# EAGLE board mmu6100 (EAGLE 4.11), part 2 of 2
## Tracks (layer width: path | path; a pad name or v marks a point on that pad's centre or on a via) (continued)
MA6  (via drill 0.61) (continued)
  Bottom 0.254: v95.89,80.64 96.52,81.28 114.3,81.28 v114.94,80.64 | v135.89,69.85 v119.38,69.85 | v139.06,73.66 149.86,73.66 150.5,74.3 180.97,74.3 v181.61,73.66 | IC39.5 161.29,106.68 162.56,105.41 176.53,105.41 177.8,106.68 IC38.5
MA7  (via drill 0.61)
  Top 0.254: v87.63,45.72 87,45.09 v87,30.48 | v81.92,29.21 79.38,31.75 79.38,37.47 v76.2,40.64 | v32.38,42.55 33.02,43.18 33.02,118.75 34.92,120.65 v34.92,125.73 | v117.47,125.09 118.75,126.36 v118.75,135.89 | v139.06,130.81 139.7,130.18 v139.7,128.27 | v161.93,128.27 161.93,106.05 IC39.6
  Bottom 0.254: v87,30.48 85.72,29.21 v81.92,29.21 | v76.2,40.64 75.56,41.27 69.22,41.27 67.94,40.01 34.92,40.01 v32.38,42.55 | v34.92,125.73 36.83,127.64 80.01,127.64 81.92,125.73 94.61,125.73 95.25,126.36 97.16,126.36 99.06,124.46 109.86,124.46 110.49,125.09 v117.47,125.09 | v118.75,135.89 123.19,135.89 128.27,130.81 v139.06,130.81 | v139.7,128.27 v161.93,128.27 | v87.63,45.72 IC5.12 | IC38.6 181.61,104.14 180.97,103.5 177.16,103.5 176.53,102.87 162.56,102.87 161.29,104.14 IC39.6
MA8  (via drill 0.61)
  Top 0.254: v85.72,41.27 85.72,43.81 IC5.9 | v111.76,43.18 v109.86,41.27 | v133.35,43.18 135.25,45.09 135.25,59.05 135.89,59.69 139.06,59.69 139.06,64.14 138.43,64.77 135.25,64.77 135.25,66.67 146.05,77.47 149.22,77.47 149.22,73.03 150.5,71.75 151.13,71.75 151.13,72.39 155.57,76.83 155.57,87.63 154.94,88.27 v154.94,101.6
  Bottom 0.254: v85.72,41.27 98.42,41.27 99.06,41.91 109.22,41.91 v109.86,41.27 | v111.76,43.18 113.03,41.91 132.08,41.91 v133.35,43.18 | v154.94,101.6 IC39.7 161.93,101.6 163.19,100.33 180.34,100.33 181.61,101.6 IC38.7
MA9  (via drill 0.61)
  Top 0.254: v87,76.83 v87,53.34 | v127,77.47 130.18,80.64 v130.18,83.19 | v161.93,85.09 162.56,84.45 v162.56,81.28
  Bottom 0.254: v87,76.83 87.63,76.2 109.86,76.2 111.12,77.47 v127,77.47 | v130.18,83.19 132.08,85.09 v161.93,85.09 | v162.56,81.28 184.78,81.28 196.22,92.71 196.22,95.25 199.39,95.25 200.03,95.89 200.03,97.79 186.06,97.79 184.78,99.06 IC38.8 180.34,99.06 179.07,97.79 162.56,97.79 161.29,99.06 IC39.8 | v87,53.34 IC5.6
MA10  (via drill 0.61)
  Top 0.254: v88.27,69.22 v88.27,55.88 | v137.16,70.48 148.59,81.92 v148.59,95.25 | v161.93,92.71 161.93,94.61 IC39.9
  Bottom 0.254: v88.27,69.22 108.58,69.22 110.49,71.12 136.53,71.12 v137.16,70.48 | v148.59,95.25 157.48,95.25 158.75,96.52 IC39.9 | v88.27,55.88 IC5.5 | v161.93,92.71 184.78,92.71 184.78,94.61 IC38.9
MA11  (via drill 0.61)
  Top 0.254: v88.9,3.17 88.27,3.81 88.27,9.53 88.9,10.16 88.9,49.53 82.55,49.53 81.92,50.16 81.92,61.59 IC5.2 | v99.06,3.17 100.33,1.91 109.22,1.91 v109.22,11.43 | v205.74,7.62 210.19,12.06 210.19,41.91 208.91,43.18 208.91,46.35 210.82,48.26 210.82,100.33 v210.19,100.97 | v187.32,101.6 184.78,99.06 184.78,95.89 IC38.10
  Bottom 0.254: v88.9,3.17 89.53,2.54 98.42,2.54 v99.06,3.17 | v109.22,11.43 139.7,11.43 143.51,7.62 v205.74,7.62 | v210.19,100.97 209.55,100.33 196.85,100.33 195.58,101.6 v187.32,101.6 | IC39.10 172.72,93.98 173.99,95.25 180.34,95.25 181.61,93.98 IC38.10
MEMDX0  (via drill 0.61)
  Top 0.254: v172.72,101.6 173.35,100.97 173.35,85.72 IC39.15 175.9,83.19 v175.9,71.75 | v182.88,10.16 182.88,25.4 IC15.1 186.06,28.57 186.06,30.48 v191.77,36.2 | v147.96,10.16 143.51,14.61 143.51,18.41 144.78,19.68 SV1.35 | v180.97,71.12 182.25,69.85 182.25,62.87 v181.61,62.23 | v196.22,62.23 v196.22,40.64
  Bottom 0.254: v172.72,101.6 172.09,102.23 161.93,102.23 161.29,102.87 157.48,102.87 153.67,106.68 IC9.18 | v182.88,10.16 v147.96,10.16 | v175.9,71.75 176.53,71.12 v180.97,71.12 | v196.22,62.23 v181.61,62.23 | v196.22,40.64 v191.77,36.2
MEMDX1  (via drill 0.61)
  Top 0.254: 156.21,81.92 156.21,80.64 157.48,79.38 158.75,79.38 158.75,82.55 158.12,83.19 158.12,84.45 IC39.13 | 156.21,81.92 156.21,88.27 155.57,88.9 155.57,97.79 156.21,98.42 156.21,101.6 153.67,104.14 IC9.17 | v20.95,120.65 20.95,130.18 IC3.6 | v63.5,80.64 v63.5,114.94 | 156.21,81.92 v156.84,81.92 | v142.88,34.29 142.88,25.4 144.78,23.5 SV1.33 | v170.81,33.02 174.62,36.83 174.62,78.11 175.26,78.74 175.26,81.28 172.72,83.82 v172.72,85.09
  Bottom 0.254: v20.95,120.65 26.67,114.94 v63.5,114.94 | v63.5,80.64 64.14,80.01 78.74,80.01 79.38,80.64 81.92,80.64 83.82,82.55 92.71,82.55 93.98,83.82 117.47,83.82 119.38,81.92 v156.84,81.92 | v142.88,34.29 163.19,34.29 164.47,33.02 v170.81,33.02 | v172.72,85.09 171.45,86.36 IC39.13
MEMDX2  (via drill 0.61)
  Top 0.254: v154.31,87.63 154.31,99.69 IC9.16 | v24.77,120.65 24.77,137.79 IC3.3 | v146.69,118.11 147.32,117.47 147.32,103.5 v146.69,102.87 | v150.5,27.94 149.86,28.57 149.86,33.66 155.57,39.37 v155.57,40.64 | v161.93,40.64 164.47,43.18 164.47,61.59 165.1,62.23 165.1,67.94 164.47,68.58 164.47,88.27 v163.83,88.9
  Bottom 0.254: v154.31,87.63 155.57,88.9 IC39.12 v163.83,88.9 | v24.77,120.65 77.47,120.65 78.11,120.02 92.71,120.02 93.34,119.38 112.39,119.38 113.67,118.11 v146.69,118.11 | v146.69,102.87 147.96,101.6 IC9.16 | v150.5,27.94 149.22,26.67 146.69,26.67 145.41,25.4 SV1.31 | v161.93,40.64 v155.57,40.64
MEMDX3  (via drill 0.61)
  Top 0.254: v88.9,140.97 94.61,140.97 95.89,142.24 97.16,142.24 v97.16,138.43 | v141.6,140.97 v139.06,138.43 | v146.69,140.97 148.59,139.06 v148.59,135.89 | v163.19,135.89 165.74,133.35 165.74,113.67 165.1,113.03 165.1,95.89 v165.74,95.25 | v170.18,91.44 v170.18,95.25 | v146.05,36.83 146.05,29.84 144.78,28.57 SV1.29 | v161.93,36.83 165.1,40.01 165.1,60.96 165.74,61.59 165.74,68.58 165.1,69.22 v165.1,91.44
  Bottom 0.254: IC9.11 153.67,88.9 156.21,91.44 IC39.11 v165.1,91.44 v170.18,91.44 | v88.9,140.97 74.93,140.97 72.39,138.43 44.45,138.43 41.91,140.97 25.4,140.97 24.13,142.24 IC3.2 | v139.06,138.43 v97.16,138.43 | v146.69,140.97 v141.6,140.97 | v163.19,135.89 v148.59,135.89 | v170.18,95.25 v165.74,95.25 | v161.93,36.83 v146.05,36.83
MEMDX4  (via drill 0.61)
  Top 0.254: v24.77,33.02 24.77,17.14 IC2.7 | v136.53,33.66 135.89,34.29 135.89,43.18 IC6.11 139.06,45.09 139.06,52.07 140.34,53.34 v140.34,65.41 | v196.22,66.04 196.22,92.08 IC38.19 | v140.34,33.02 v140.34,30.48
  Bottom 0.254: v24.77,33.02 26.04,34.29 30.48,34.29 31.75,33.02 117.47,33.02 118.11,33.66 v136.53,33.66 139.7,33.66 v140.34,33.02 | v196.22,66.04 195.58,65.41 v140.34,65.41 | v140.34,30.48 SV1.27
MEMDX5  (via drill 0.61)
  Top 0.254: v19.68,31.75 20.32,31.11 20.32,20.32 IC2.6 | IC6.12 135.25,43.81 135.25,24.77 135.89,24.13 141.6,24.13 141.6,34.29 142.88,35.56 143.51,35.56 143.51,34.92 144.78,33.66 SV1.25 | v196.85,37.47 197.49,38.1 197.49,65.41 200.03,67.94 200.03,89.53 IC38.18
  Bottom 0.254: v19.68,31.75 22.86,34.92 31.11,34.92 32.38,33.66 116.84,33.66 117.47,34.29 135.89,34.29 136.53,34.92 140.97,34.92 142.88,33.02 SV1.25 145.41,33.02 146.69,31.75 196.85,31.75 v196.85,37.47
MEMDX6  (via drill 0.61)
  Top 0.254: v26.04,36.2 v26.04,25.4 | v132.72,35.56 132.08,36.2 132.08,43.18 132.72,43.81 132.72,47.62 v133.35,48.26 133.99,48.9 133.99,52.7 133.35,53.34 133.35,61.59 133.99,62.23 133.99,78.11 v134.62,78.74
  Bottom 0.254: v26.04,36.2 26.67,35.56 31.75,35.56 33.02,34.29 116.2,34.29 116.84,34.92 132.72,34.92 | 132.72,34.92 135.25,34.92 135.89,35.56 SV1.23 | v26.04,25.4 IC2.3 | v132.72,35.56 132.72,34.92 | v133.35,48.26 IC6.13 | v134.62,78.74 135.25,78.11 146.69,78.11 147.96,76.83 178.44,76.83 179.71,78.11 186.06,78.11 196.85,88.9 IC38.17
MEMDX7  (via drill 0.61)
  Top 0.254: v27.3,36.83 v27.3,30.48 | v141.6,50.8 v141.6,38.1 | v132.72,77.47 v132.72,52.7
  Bottom 0.254: v27.3,30.48 26.67,30.48 24.13,27.94 IC2.2 | v27.3,36.83 27.94,36.2 32.38,36.2 33.02,35.56 40.01,35.56 40.64,34.92 78.11,34.92 78.74,35.56 101.6,35.56 102.23,34.92 115.57,34.92 116.2,35.56 131.44,35.56 132.72,36.83 141.6,36.83 | 141.6,36.83 142.88,36.83 144.15,38.1 SV1.21 | v141.6,38.1 141.6,36.83 | v141.6,50.8 IC6.14 134.62,50.8 v132.72,52.7 | v132.72,77.47 146.05,77.47 147.32,76.2 179.07,76.2 180.34,77.47 187.96,77.47 196.85,86.36 IC38.16
MEMDX8  (via drill 0.61)
  Top 0.254: 130.81,16.51 133.99,19.68 133.99,38.73 v133.35,39.37 | 130.81,16.51 IC1.7 | v140.34,52.07 140.34,43.81 140.97,43.18 140.97,40.64 v140.34,40.01 | v149.86,6.35 139.7,16.51 130.81,16.51
  Bottom 0.254: v133.35,39.37 133.99,40.01 137.16,40.01 137.79,40.64 140.34,40.64 | 140.34,40.64 SV1.19 | v140.34,52.07 139.7,52.07 138.43,53.34 IC6.15 | 140.34,40.64 v140.34,40.01 | v149.86,6.35 213.36,6.35 213.36,68.58 IC38.15
MEMDX9  (via drill 0.61)
  Top 0.254: v133.35,17.78 134.62,19.05 134.62,41.27 v133.99,41.91 | SV1.17 144.78,43.81 146.05,45.09 v146.05,54.61 v146.05,76.2 | v184.78,76.2 184.78,84.45 IC38.13
  Bottom 0.254: v133.99,41.91 141.6,41.91 142.88,43.18 SV1.17 | v133.35,17.78 IC1.6 | v146.05,54.61 139.7,54.61 138.43,55.88 IC6.16 | v184.78,76.2 180.34,76.2 179.71,75.56 146.69,75.56 v146.05,76.2
MEMDX10  (via drill 0.61)
  Top 0.254: v139.06,26.67 139.06,36.83 136.53,39.37 136.53,40.01 v139.7,43.18 | v144.78,74.93 139.06,69.22 139.06,65.41 139.7,64.77 139.7,58.42 IC6.17 | v181.61,74.93 180.97,75.56 180.97,87 IC38.12
  Bottom 0.254: v139.06,26.67 132.08,26.67 130.81,25.4 IC1.3 | v139.7,43.18 142.24,45.72 SV1.15 145.41,45.72 146.69,44.45 170.81,44.45 172.09,45.72 201.93,45.72 206.38,50.16 206.38,52.07 209.55,52.07 210.82,53.34 210.82,69.85 186.69,69.85 v181.61,74.93 v144.78,74.93
MEMDX11  (via drill 0.61)
  Top 0.254: v131.44,46.99 131.44,29.84 IC1.2 | v133.99,46.99 134.62,47.62 134.62,59.69 135.89,60.96 IC6.18 | v171.45,82.55 172.09,81.92 v172.09,62.23
  Bottom 0.254: v131.44,46.99 v133.99,46.99 140.97,46.99 142.24,48.26 SV1.13 | v171.45,82.55 184.78,82.55 184.78,89.53 IC38.11 | v172.09,62.23 152.4,62.23 149.86,59.69 139.7,59.69 138.43,60.96 IC6.18
MEMSEL\  (via drill 0.61)
  Top 0.254: IC36.9 179.71,52.7 179.71,56.52 IC36.12 179.71,60.33 v179.71,97.16 | v57.78,83.82 v57.78,142.24 | v135.25,92.71 133.99,91.44 133.99,80.64 131.44,78.11 v128.91,78.11 | v88.9,78.74 86.36,81.28 v86.36,85.09
  Bottom 0.254: IC38.20 186.06,96.52 184.78,97.79 181.61,97.79 180.97,97.16 v179.71,97.16 177.16,97.16 176.53,96.52 IC39.20 162.56,96.52 161.29,95.25 158.75,95.25 156.21,92.71 v135.25,92.71 | CPU.37 v57.78,83.82 58.42,84.45 85.72,84.45 v86.36,85.09 | v57.78,142.24 IC10.13 | v128.91,78.11 128.27,78.74 115.57,78.74 114.94,78.11 109.22,78.11 108.58,78.74 106.05,78.74 104.78,77.47 90.17,77.47 v88.9,78.74
N$2
  Top 0.254: QG1.1 QG2.1
N$3  (via drill 0.61)
  Top 0.254: v142.24,19.05 138.43,22.86 IC1.13 | IC2.13 28.57,24.77 v28.57,33.02 28.57,135.25 IC3.13 | v118.11,32.38 v118.11,24.13
  Bottom 0.254: IC1.13 IC1.4 124.46,22.86 123.19,24.13 v118.11,24.13 | v142.24,19.05 172.72,19.05 175.26,16.51 182.88,16.51 184.15,15.24 IC15.6 | IC2.4 IC2.13 | IC3.13 IC3.4 | v118.11,32.38 29.21,32.38 v28.57,33.02
N$4  (via drill 0.61)
  Top 0.254: 74.3,107.31 74.3,65.41 IC27.19 | 74.3,107.31 IC30.19 | v182.88,71.12 182.88,53.34 IC35.6 | v170.81,73.03 169.54,74.3 169.54,90.81 168.91,91.44 168.91,97.16 170.81,99.06 170.81,132.72 171.45,133.35 171.45,143.51 v165.1,149.86 | v136.53,149.22 v132.08,144.78 | v104.14,143.51 102.23,145.41 v102.23,147.96 | v92.08,147.96 86.36,142.24 86.36,137.16 85.09,135.89 80.01,135.89 80.01,124.46 74.3,118.75 74.3,107.31
  Bottom 0.254: v182.88,71.12 180.97,73.03 v170.81,73.03 | v165.1,149.86 164.47,149.22 158.12,149.22 157.48,148.59 137.16,148.59 v136.53,149.22 | v132.08,144.78 130.81,143.51 v104.14,143.51 | v102.23,147.96 v92.08,147.96
N$5
  Bottom 0.254: IC15.11 194.31,20.32 195.58,21.59 205.74,21.59 207.01,20.32 IC18.11
N$6  (via drill 0.61)
  Top 0.254: v178.44,69.85 177.16,71.12 177.16,114.94 v177.8,115.57 | v65.41,115.57 64.77,116.2 v64.77,137.16
  Bottom 0.254: v178.44,69.85 182.88,69.85 185.42,67.31 197.49,67.31 197.49,61.59 IC20.3 | v177.8,115.57 158.75,115.57 153.67,110.49 140.97,110.49 138.43,113.03 133.35,113.03 132.72,112.39 131.44,112.39 130.81,113.03 111.12,113.03 109.86,111.76 93.98,111.76 91.44,114.3 73.03,114.3 71.75,115.57 v65.41,115.57 | v64.77,137.16 IC10.11
N$7  (via drill 0.61)
  Top 0.254: v167,50.16 168.28,48.9 v168.28,46.99 | v127,44.45 126.36,43.81 v126.36,39.37 | v99.06,40.64 95.25,44.45 95.25,60.96 97.16,62.87 v97.16,88.9
  Bottom 0.254: v167,50.16 166.37,49.53 160.66,49.53 160.66,51.44 161.29,52.07 164.47,52.07 164.47,53.98 IC29.11 | v168.28,46.99 167,45.72 149.22,45.72 147.96,46.99 142.24,46.99 139.7,44.45 v127,44.45 | v126.36,39.37 125.73,40.01 111.76,40.01 111.12,39.37 102.23,39.37 100.97,40.64 v99.06,40.64 | v97.16,88.9 95.89,90.17 87.63,90.17 85.09,92.71 16.51,92.71 IC31.5
N$8  (via drill 0.61)
  Top 0.254: v117.47,129.54 v117.47,132.08 | v127.64,128.27 127.64,122.56 128.91,121.28 128.91,112.39 IC21.1
  Bottom 0.254: v117.47,129.54 118.75,128.27 v127.64,128.27 | v117.47,132.08 IC16.6
N$9  (via drill 0.61)
  Top 0.254: v109.86,69.22 109.86,66.67 IC32.19 | v166.37,69.22 v166.37,55.24 | v181.61,55.88 v181.61,58.42
  Bottom 0.254: v109.86,69.22 110.49,68.58 147.96,68.58 148.59,69.22 v166.37,69.22 | v166.37,55.24 168.28,53.34 IC36.5 171.45,53.34 172.72,54.61 180.34,54.61 v181.61,55.88 | v181.61,58.42 IC35.3
N$12  (via drill 0.61)
  Top 0.254: v62.87,69.85 62.87,65.41 IC37.19 | v166.37,70.48 167.64,69.22 167.64,57.78 167,57.15 168.28,55.88 IC36.4
  Bottom 0.254: v62.87,69.85 63.5,70.48 87,70.48 88.27,71.75 142.24,71.75 144.15,69.85 146.69,69.85 147.96,71.12 151.76,71.12 153.03,69.85 165.74,69.85 v166.37,70.48 | IC35.8 198.12,48.26 199.39,46.99 201.93,46.99 202.56,47.62 202.56,52.07 199.39,52.07 194.31,57.15 172.72,57.15 171.45,55.88 IC36.4
N$14  (via drill 0.61)
  Top 0.254: v100.97,78.74 100.97,57.78 IC32.5 | v90.17,79.38 88.27,81.28 v88.27,85.09 | v127.64,84.45 133.35,90.17 133.35,95.25 135.25,97.16 135.25,132.72 135.89,133.35 139.7,133.35 139.7,135.89 v140.97,137.16
  Bottom 0.254: v100.97,78.74 100.33,78.11 91.44,78.11 v90.17,79.38 | v88.27,85.09 88.9,84.45 89.53,84.45 90.81,85.72 123.83,85.72 125.09,84.45 v127.64,84.45 | v140.97,137.16 IC34.4
N$15  (1 unrouted)
N$19  (via drill 0.61)
  Top 0.254: v101.6,57.15 101.6,55.88 IC32.6 | v158.12,78.11 v158.12,59.69 | v154.31,78.11 150.5,81.92 150.5,104.78 151.13,105.41 154.31,105.41 154.31,114.94 v153.67,115.57 | v146.05,116.2 145.41,116.84 145.41,121.28 146.69,122.56 146.69,127.64 IC34.7
  Bottom 0.254: v101.6,57.15 118.11,57.15 120.65,54.61 125.73,54.61 128.27,52.07 130.81,52.07 135.89,57.15 151.13,57.15 153.67,59.69 v158.12,59.69 | v154.31,78.11 v158.12,78.11 | v153.67,115.57 153.03,116.2 v146.05,116.2
N$22  (via drill 0.61)
  Top 0.254: v102.23,78.74 102.87,78.11 102.87,54.61 IC32.7 | v105.41,79.38 107.31,81.28 107.31,121.28 109.22,123.19 109.22,138.43 111.12,140.34 v111.12,140.97 | v132.72,134.62 v132.72,140.97 | v140.97,133.35 142.24,134.62 v142.24,138.43 | v154.31,138.43 154.31,128.91 IC34.9
  Bottom 0.254: v102.23,78.74 102.87,79.38 v105.41,79.38 | v132.72,140.97 v111.12,140.97 | v132.72,134.62 133.99,133.35 v140.97,133.35 | v142.24,138.43 v154.31,138.43
N$23  (via drill 0.61)
  Top 0.254: v163.19,120.65 163.19,89.53 162.56,88.9 162.56,85.72 163.83,84.45 163.83,64.77 164.47,64.14 164.47,62.87 IC29.13 | v121.92,120.65 IC16.8
  Bottom 0.254: v121.92,120.65 123.19,119.38 151.13,119.38 152.4,120.65 v163.19,120.65
N$24
  Bottom 0.254: IC36.3 171.45,58.42 175.26,62.23 180.34,62.23 181.61,63.5 IC35.1
N$25  (via drill 0.61)
  Top 0.254: v64.77,101.6 v64.77,109.22 | v10.79,121.28 v10.79,100.97 | v79.38,149.22 84.45,149.22 84.45,151.13 163.19,151.13 163.19,146.69 166.37,143.51 v170.18,143.51 | v185.42,144.78 v187.96,142.24 | v193.04,142.24 194.94,140.34 v194.94,134.62 | v208.28,133.35 208.28,135.89 209.55,137.16 214,137.16 214,13.34 v212.09,11.43 | v173.35,38.1 v173.35,50.8
  Bottom 0.254: v64.77,101.6 63.5,100.33 57.15,100.33 54.61,97.79 13.97,97.79 v10.79,100.97 | v10.79,121.28 5.71,126.36 5.71,149.86 63.5,149.86 64.77,148.59 78.74,148.59 v79.38,149.22 | v170.18,143.51 184.15,143.51 v185.42,144.78 | v187.96,142.24 189.23,140.97 191.77,140.97 v193.04,142.24 | v194.94,134.62 196.22,133.35 v208.28,133.35 | v212.09,11.43 212.09,41.91 182.88,41.91 179.07,38.1 v173.35,38.1 | v64.77,109.22 IC33.19 | v173.35,50.8 IC36.6
N$26  (via drill 0.61)
  Top 0.254: v39.37,110.49 43.81,114.94 43.81,137.79 IC40.12
  Bottom 0.254: v39.37,110.49 17.78,110.49 16.51,109.22 IC31.13 | IC11.13 74.93,142.24 73.66,140.97 48.26,140.97 46.99,139.7 IC40.12
N$27  (via drill 0.61)
  Top 0.254: v73.66,126.36 73.66,137.16 IC11.12 | v156.21,123.83 158.12,125.73 158.12,132.72 IC41.5
  Bottom 0.254: v73.66,126.36 74.93,125.09 95.25,125.09 95.89,125.73 96.52,125.73 98.42,123.83 110.49,123.83 111.12,124.46 116.84,124.46 117.47,123.83 118.75,123.83 119.38,124.46 132.08,124.46 132.72,123.83 149.22,123.83 149.86,124.46 155.57,124.46 v156.21,123.83
N$28  (1 unrouted)
N$29
  Top 0.254: IC23.4 189.87,136.53 189.87,135.25 IC23.5
  Bottom 0.254: IC22.8 184.15,129.54 185.42,128.27 191.77,128.27 192.41,128.91 192.41,133.99 191.13,133.99 IC23.5
N$30
  Top 0.254: IC23.6 192.41,130.18 192.41,115.57 191.13,114.3 191.13,65.41 190.5,64.77 190.5,40.01 189.87,39.37 198.12,31.11 198.12,12.7 199.39,11.43 202.56,11.43 202.56,18.41 IC18.4
N$33  (via drill 0.61)
  Top 0.254: IC17.4 98.42,23.5 98.42,24.77 IC17.3 | v102.87,17.78 v102.87,22.86
  Bottom 0.254: v102.87,17.78 IC17.9 | v102.87,22.86 IC17.4
OE\  (via drill 0.61)
  Top 0.254: v173.35,55.88 173.99,56.52 173.99,78.74 174.62,79.38 174.62,80.64 171.45,83.82 171.45,101.6 172.72,102.87 174.62,102.87 174.62,102.23 IC39.22
  Bottom 0.254: v173.35,55.88 IC36.11 | IC38.22 196.85,101.6 195.58,102.87 177.8,102.87 176.53,101.6 IC39.22
OPR\  (via drill 0.61)
  Top 0.254: IC4.5 67.94,20.95 67.94,22.23 IC4.4 | v11.43,125.73 12.7,124.46 v12.7,90.81 | v52.7,85.09 54.61,83.19 54.61,67.31 55.24,66.67 55.24,43.81 57.78,41.27 57.78,18.41 59.05,17.14 59.05,9.53 59.69,8.89 66.67,8.89 66.67,13.34 67.31,13.97 72.39,13.97 v72.39,15.24
  Bottom 0.254: v12.7,90.81 18.41,85.09 v52.7,85.09 | v72.39,15.24 72.39,19.68 69.22,19.68 IC4.5 | v11.43,125.73 IC7.7
OSCOUT
  Top 0.254: 15.24,57.78 QG2.8
  Bottom 0.254: QG2.8 CPU.14
OSR\  (via drill 0.61)
  Top 0.254: v67.94,41.27 70.48,38.73 70.48,17.14 69.85,16.51 70.48,15.88 70.48,15.24 71.12,15.24 72.39,16.51 72.39,17.78 IC4.11 | v40.64,41.27 39.37,40.01 39.37,31.75 40.01,31.11 40.01,29.84 IC8.2
  Bottom 0.254: v67.94,41.27 67.31,40.64 58.42,40.64 56.52,42.55 55.24,42.55 54.61,41.91 49.53,41.91 48.9,42.55 47.62,42.55 46.35,41.27 v40.64,41.27
OSRHLT\  (via drill 0.61)
  Top 0.254: v39.37,11.43 39.37,12.7 40.01,13.34 40.01,20.95 IC8.4
  Bottom 0.254: v39.37,11.43 73.66,11.43 74.93,12.7 IC4.9
POPR  (via drill 0.61)
  Top 0.254: v41.91,17.78 43.18,19.05 43.18,46.35 42.55,46.99 v42.55,66.04 | v49.53,68.58 49.53,138.43 IC10.2
  Bottom 0.254: v42.55,66.04 45.09,68.58 v49.53,68.58 | IC8.6 v41.91,17.78
RDF\  (via drill 0.61)
  Top 0.254: v158.12,25.4 v158.12,57.15
  Bottom 0.254: v158.12,25.4 IC14.14 | IC29.3 156.84,58.42 v158.12,57.15 165.1,57.15 168.91,60.96 IC36.2
RESET\  (via drill 0.61)
  Top 0.254: IC18.1 201.29,28.57 201.29,30.48 202.56,31.75 v202.56,57.15 198.75,57.15 198.75,64.14 201.29,66.67 201.29,127 v200.66,127.64 | CPU.7 PAD7.1 24.77,76.83 24.77,80.01 21.59,80.01 20.95,80.64 20.95,92.08 26.04,97.16 26.04,149.22 32.38,149.22 36.83,144.78 IC40.1 | v50.16,30.48 50.8,31.11 v50.8,72.39 | v164.47,128.27 161.93,130.81 161.93,145.41 v157.48,149.86 | v74.93,149.86 69.85,144.78 IC11.1
  Bottom 0.254: IC26.5 172.72,17.78 176.53,13.97 204.47,13.97 207.01,16.51 209.55,16.51 210.19,17.14 210.19,24.77 208.91,24.77 IC18.13 207.01,25.4 204.47,27.94 IC18.1 | v202.56,57.15 198.12,57.15 194.31,60.96 IC35.13 | IC40.1 39.37,144.78 40.64,143.51 66.04,143.51 67.31,144.78 IC11.1 | v50.8,72.39 48.26,74.93 26.67,74.93 PAD7.1 | v50.16,30.48 IC42.1 | v200.66,127.64 169.54,127.64 168.91,128.27 v164.47,128.27 | v157.48,149.86 156.84,150.5 75.56,150.5 v74.93,149.86
RIB\
  Top 0.254: IC14.12 160.66,22.23 160.66,48.9 IC29.9
  Bottom 0.254: IC35.9 191.77,50.8 190.5,52.07 165.74,52.07 164.47,50.8 IC29.9
RIF\  (via drill 0.61)
  Top 0.254: v157.48,22.86 156.84,23.5 156.84,51.44 IC29.5 | v149.86,133.35 149.86,139.7 IC34.1 | v169.54,133.35 170.18,132.72 170.18,99.69 168.28,97.79 168.28,88.27 168.91,87.63 168.91,66.67 | 168.91,66.67 168.91,63.5 IC36.1 | v149.22,53.34 149.22,64.77 v151.13,66.67 | 168.91,66.67 v170.18,66.67
  Bottom 0.254: v157.48,22.86 IC14.13 | v169.54,133.35 v149.86,133.35 | v151.13,66.67 151.76,66.04 169.54,66.04 v170.18,66.67 | v149.22,53.34 IC29.5
RMF\  (via drill 0.61)
  Top 0.254: IC48.17 123.83,106.05 123.83,107.31 IC48.19 | v116.84,109.22 IC48.1 | v36.2,109.22 36.2,132.72 IC40.5 | v164.47,34.29 164.47,19.68 IC14.11 | v195.58,34.92 198.12,37.47 198.12,64.77 200.66,67.31 200.66,126.36 199.39,127.64 199.39,128.27 200.03,128.91 v200.03,138.43 | v166.37,113.03 169.54,116.2 169.54,130.18 IC41.11
  Bottom 0.254: IC40.5 39.37,134.62 41.91,137.16 IC40.11 | IC48.19 v116.84,109.22 115.57,107.95 97.79,107.95 95.25,110.49 44.45,110.49 43.18,109.22 v36.2,109.22 | v164.47,34.29 165.1,34.92 v195.58,34.92 | 185.42,138.43 v200.03,138.43 | 185.42,138.43 184.15,139.7 IC22.12 | 185.42,138.43 165.74,138.43 165.74,136.53 166.37,135.89 168.91,135.89 170.81,133.99 170.81,133.35 169.54,132.08 IC41.11 | v166.37,113.03 158.75,113.03 153.67,107.95 151.13,107.95 148.59,105.41 127,105.41 126.36,104.78 123.83,104.78 123.19,104.14 IC48.17
RTF\  (via drill 0.61)
  Top 0.254: v126.36,135.25 v126.36,139.7 | v131.44,133.35 132.72,132.08 v132.72,129.54 | IC46.17 120.02,60.33 120.02,61.59 IC46.19 123.83,65.41 123.83,92.71 v124.46,93.34 | v102.23,49.53 102.87,48.9 102.87,41.91 96.52,35.56 96.52,20.32 IC13.10 | v109.22,49.53 110.49,50.8 110.49,57.78 109.86,58.42 109.86,62.87 110.49,63.5 110.49,64.14 v109.86,64.77 | v140.97,129.54 140.97,125.73 139.7,124.46 v139.7,96.52
  Bottom 0.254: 170.18,130.81 168.91,129.54 IC41.10 | 170.18,130.81 180.34,130.81 181.61,132.08 IC22.9 | v126.36,135.25 128.27,133.35 v131.44,133.35 | v132.72,129.54 133.99,128.27 138.43,128.27 140.34,130.18 | 140.34,130.18 140.97,130.81 170.18,130.81 | v126.36,139.7 IC16.12 | v109.22,49.53 v102.23,49.53 | v109.86,64.77 111.12,66.04 IC46.1 115.57,66.04 118.11,63.5 IC46.19 | 140.34,130.18 v140.97,129.54 | v139.7,96.52 138.43,95.25 133.35,95.25 130.81,92.71 125.09,92.71 v124.46,93.34
RUN
  Top 0.254: CPU.2 PAD6.1
RUNHLT\  (via drill 0.61)
  Top 0.254: v17.14,13.34 17.14,32.38 24.77,40.01 24.77,54.61 21.59,54.61 20.95,55.24 20.95,76.83 CPU.6 | v93.98,16.51 97.16,19.68 97.16,31.11 v102.23,36.2 | v139.06,39.37 141.6,36.83 143.51,36.83 143.51,41.27 144.15,41.91 143.51,42.55 143.51,48.9 144.15,49.53 143.51,50.16 143.51,51.44 144.78,52.7 SV1.9
  Bottom 0.254: v17.14,13.34 21.59,8.89 74.93,8.89 82.55,16.51 v93.98,16.51 | v102.23,36.2 130.81,36.2 132.08,37.47 137.16,37.47 v139.06,39.37
SETZF\  (via drill 0.61)
  Top 0.254: IC18.10 206.38,17.78 205.1,19.05 v205.1,63.5 204.47,64.14 204.47,146.69 182.25,146.69 178.44,142.88 178.44,135.25 IC22.6
  Bottom 0.254: IC20.1 v205.1,63.5
SF0  (via drill 0.61)  (1 unrouted)
  Top 0.254: v59.05,46.99 59.05,22.23 IC42.16
  Bottom 0.254: v59.05,46.99 57.78,48.26 IC37.8
SF1  (via drill 0.61)
  Top 0.254: IC42.15 58.42,20.32 58.42,41.91 57.78,42.55 57.78,49.53 v56.52,50.8 56.52,71.12 v62.87,77.47 | v110.49,99.06 110.49,80.64 108.58,78.74 v108.58,77.47
  Bottom 0.254: v56.52,50.8 IC37.7 | v108.58,77.47 107.95,76.83 88.27,76.83 87,78.11 80.64,78.11 80.01,77.47 v62.87,77.47 | v110.49,99.06 IC48.6
SF2  (via drill 0.61)
  Top 0.254: v62.87,52.07 62.87,43.18 64.14,41.91 64.14,24.13 62.87,22.86 62.87,12.06 IC42.12 | v110.49,106.68 113.03,104.14 IC48.4 | v48.26,107.95 48.26,90.81 43.81,86.36 v43.81,52.07
  Bottom 0.254: v62.87,52.07 59.69,52.07 59.05,52.7 55.24,52.7 54.61,53.34 IC37.6 48.9,53.34 47.62,52.07 v43.81,52.07 | v110.49,106.68 109.86,107.31 93.34,107.31 92.71,107.95 v48.26,107.95
SF3  (via drill 0.61)
  Top 0.254: v36.83,10.16 36.2,10.79 v36.2,37.47 v36.2,52.07 | v103.5,109.22 103.5,100.97 102.87,100.33 99.69,100.33 99.69,95.25 103.5,91.44 103.5,41.27 v100.33,38.1
  Bottom 0.254: v36.2,52.07 39.37,52.07 41.91,54.61 50.8,54.61 52.07,55.88 IC37.5 | v36.83,10.16 IC42.9 | v100.33,38.1 78.74,38.1 78.11,38.73 74.3,38.73 71.75,36.2 43.18,36.2 41.91,37.47 v36.2,37.47 | v103.5,109.22 IC48.2
SF4  (via drill 0.61)
  Top 0.254: 51.44,56.52 51.44,19.68 IC42.6 | 51.44,56.52 IC37.4 | v126.36,97.79 126.36,83.82 v127,83.19 | v69.22,81.92 66.67,79.38 v66.67,76.2 | v52.07,74.93 52.07,67.31 51.44,66.67 51.44,56.52
  Bottom 0.254: v126.36,97.79 124.46,97.79 123.19,99.06 IC48.15 | v127,83.19 119.38,83.19 118.11,84.45 92.08,84.45 90.81,83.19 70.48,83.19 v69.22,81.92 | v66.67,76.2 65.41,74.93 v52.07,74.93
SF5  (via drill 0.61)
  Top 0.254: v48.26,59.69 48.26,44.45 47.62,43.81 47.62,41.27 48.26,40.64 48.26,16.51 54.61,16.51 55.24,17.14 55.24,18.41 IC42.5 | v118.75,93.98 119.38,93.34 v119.38,84.45 | v64.77,60.96 v64.77,81.92
  Bottom 0.254: v48.26,59.69 48.9,60.33 52.7,60.33 IC37.3 58.42,60.96 59.69,59.69 63.5,59.69 v64.77,60.96 | v119.38,84.45 118.75,85.09 91.44,85.09 90.17,83.82 67.31,83.82 65.41,81.92 v64.77,81.92 | v118.75,93.98 IC48.13
SF6  (via drill 0.61)
  Top 0.254: v50.16,27.94 48.9,29.21 48.9,40.01 50.16,41.27 50.16,62.23 v49.53,62.87 48.26,64.14 48.26,71.12 46.99,72.39 46.99,75.56 v47.62,76.2 | v121.92,73.66 IC48.11
  Bottom 0.254: v49.53,62.87 50.16,63.5 IC37.2 | v50.16,27.94 IC42.2 | v121.92,73.66 121.28,73.03 51.44,73.03 48.26,76.2 v47.62,76.2
SINT\  (1 unrouted)
SKP\  (via drill 0.61)
  Top 0.254: v80.01,78.74 83.82,74.93 v83.82,71.75 | v161.29,71.12 160.66,70.48 160.66,60.33 IC29.12 | v150.5,35.56 151.76,36.83 151.76,41.27 152.4,41.91 v152.4,71.75
  Bottom 0.254: v83.82,71.75 84.45,72.39 142.88,72.39 144.78,70.48 146.05,70.48 147.32,71.75 v152.4,71.75 156.21,71.75 156.84,71.12 v161.29,71.12 | CPU.35 v80.01,78.74 | v150.5,35.56 SV1.24
SUF\  (via drill 0.61)
  Top 0.254: v81.28,134.62 82.55,133.35 85.72,133.35 85.72,97.16 v86.36,96.52 | v104.14,96.52 104.14,31.75 101.6,29.21 101.6,15.88 v102.87,14.61 | v210.82,132.72 213.36,130.18 213.36,13.97 205.74,6.35 168.28,6.35 v168.28,16.51
  Bottom 0.254: v86.36,96.52 87.63,95.25 92.71,95.25 93.34,95.89 98.42,95.89 100.33,97.79 102.87,97.79 v104.14,96.52 | v102.87,14.61 103.5,13.97 125.73,13.97 128.27,16.51 152.4,16.51 | 152.4,16.51 153.67,15.24 IC14.7 | v81.28,134.62 IC11.10 | v210.82,132.72 200.03,143.51 185.42,143.51 184.15,142.24 IC22.13 | v168.28,16.51 152.4,16.51
SWSEL\
  Top 0.254: PAD8.1 CPU.31
TAD\
  Top 0.254: IC7.14 PAD2.1
UB  (via drill 0.61)
  Top 0.254: IC41.4 159.38,137.79 159.38,139.06 IC41.3 159.38,140.34 159.38,141.6 IC41.2 159.38,142.88 159.38,144.15 IC41.1 154.31,150.5 85.09,150.5 85.09,148.59 83.19,146.69 80.01,146.69 80.01,143.51 80.64,142.88 80.64,139.06 78.11,136.53 78.11,133.99 IC11.9 | v71.75,114.3 72.39,114.94 v72.39,132.08
  Bottom 0.254: IC41.12 166.37,134.62 163.83,137.16 IC41.4 | IC41.2 IC41.15 | v71.75,114.3 71.12,113.67 63.5,113.67 62.87,114.3 13.34,114.3 13.34,108.58 IC31.12 | IC11.9 v72.39,132.08
UIF\  (via drill 0.61)
  Top 0.254: v103.5,132.72 104.78,133.99 v104.78,135.89
  Bottom 0.254: v103.5,132.72 102.87,133.35 71.12,133.35 69.85,132.08 IC11.6 | v104.78,135.89 117.47,135.89 118.75,134.62 IC16.10
USER_MODE  (via drill 0.61)
  Top 0.254: v64.14,22.86 64.77,23.5 64.77,46.99 v64.14,47.62 64.14,57.15 63.5,57.78 63.5,69.22 64.14,69.85 64.14,77.47 62.23,79.38 55.24,79.38 v55.24,100.33 55.88,100.97 55.88,142.24 IC10.1
  Bottom 0.254: v64.14,47.62 64.77,48.26 IC27.8 | IC42.17 v64.14,22.86 | v55.24,100.33 17.78,100.33 16.51,99.06 IC31.9
VCC  (via drill 0.61)
  Top 0.254: IC28.16 93.98,144.78 98.42,149.22 106.05,149.22 106.05,145.41 IC24.16 | IC7.16 17.78,144.78 19.68,142.88 19.68,137.79 IC3.5 17.14,128.91 17.14,113.67 IC31.14 13.34,109.86 13.34,103.5 IC31.10 | v79.38,142.88 77.47,144.78 IC11.14 | v116.84,111.76 115.57,113.03 108.58,113.03 v108.58,114.3 | v92.71,114.3 92.08,113.67 92.08,112.39 IC19.20 | v127,30.48 127.64,29.84 127.64,22.23 IC1.5 | IC17.12 106.05,26.04 106.05,27.3 IC17.13 106.05,28.57 106.05,29.84 IC17.14 | 93.34,26.67 93.34,28.57 IC13.16 | 93.34,26.67 v93.34,19.05 | 93.34,26.67 v93.98,26.67 | v116.84,27.94 v116.84,30.48 | 5.71,107.31 5.71,106.05 IC31.4 | 5.71,107.31 IC31.2 | 5.71,107.31 5.71,130.18 IC7.6 | QG2.14 QG1.8 15.24,65.41 13.97,64.14 13.97,30.48 IC12.14 | IC12.2 6.99,28.57 6.99,29.84 IC12.1 | v20.95,31.75 20.95,22.23 IC2.5 | IC8.9 43.81,19.68 43.81,28.57 IC8.14 | IC39.28 179.07,120.65 179.07,140.97 IC22.14 | v137.79,114.3 137.79,112.39 IC21.20 | IC23.14 197.49,144.15 197.49,142.88 IC23.13 197.49,141.6 197.49,140.34 IC23.12 196.22,137.79 196.22,128.91 196.85,128.27 196.85,118.11 IC38.28 194.31,113.03 v194.31,68.58 193.68,67.94 193.68,64.14 IC35.14 | v152.4,117.47 IC9.20 | IC20.14 207.65,62.87 207.65,61.59 IC20.13 207.65,60.33 207.65,59.05 IC20.12 207.65,57.78 207.65,56.52 IC20.11 207.65,55.24 207.65,53.98 IC20.10 206.38,51.44 206.38,29.84 IC18.14 | SV1.1 SV1.3 | IC33.1 51.44,109.86 51.44,81.92 53.34,80.01 IC37.1
  Bottom 0.254: IC16.14 120.65,144.78 119.38,146.05 113.03,146.05 111.12,144.15 107.31,144.15 IC24.16 | 48.26,146.05 46.99,144.78 IC40.14 | 48.26,146.05 58.42,146.05 59.69,144.78 IC10.14 62.23,144.78 63.5,146.05 73.66,146.05 74.93,144.78 IC11.14 | 48.26,146.05 17.78,146.05 16.51,144.78 IC7.16 | v79.38,142.88 80.01,143.51 88.9,143.51 90.17,144.78 IC28.16 | IC19.20 90.17,111.76 88.9,113.03 79.38,113.03 78.11,111.76 IC30.20 IC30.1 IC33.20 IC33.1 RN4.1 IC31.14 | v108.58,114.3 99.06,114.3 97.16,112.39 94.61,112.39 v92.71,114.3 | v116.84,111.76 IC48.20 | v127,30.48 IC47.20 v116.84,30.48 | v93.34,19.05 86.36,19.05 85.09,17.78 IC13.6 | v93.98,26.67 104.14,26.67 105.41,27.94 IC17.13 | v116.84,27.94 115.57,26.67 111.12,26.67 109.86,25.4 IC17.12 | IC31.10 13.97,101.6 11.43,104.14 IC31.4 5.71,102.23 5.71,92.08 12.7,92.08 | 12.7,92.08 20.95,92.08 21.59,91.44 CPU.1 | 12.7,92.08 11.43,90.81 11.43,73.66 QG2.14 | IC12.1 IC12.14 19.68,30.48 v20.95,31.75 48.26,31.75 | 58.42,31.75 59.69,30.48 IC42.20 | 48.26,31.75 58.42,31.75 | 48.26,31.75 46.99,30.48 IC8.14 | 73.66,31.75 74.93,30.48 IC4.16 | 58.42,31.75 73.66,31.75 | 73.66,31.75 88.9,31.75 90.17,30.48 IC13.16 | IC25.16 138.43,144.78 139.7,143.51 149.22,143.51 150.5,144.78 IC34.16 153.67,144.78 154.94,143.51 165.1,143.51 166.37,144.78 IC41.16 IC22.1 IC22.14 184.15,144.78 185.42,146.05 195.58,146.05 196.85,144.78 IC23.14 | v137.79,114.3 138.43,113.67 140.97,113.67 141.6,113.03 149.86,113.03 151.13,111.76 IC9.20 | v152.4,117.47 153.67,118.75 194.94,118.75 196.85,116.84 IC38.28 | IC20.13 IC20.2 | IC20.11 IC20.4 | 175.26,29.21 176.53,27.94 IC26.14
  Bottom 0.254: 175.26,29.21 173.99,30.48 IC14.16 | 190.5,29.21 191.77,27.94 IC15.14 | 190.5,29.21 175.26,29.21 | 190.5,29.21 205.74,29.21 207.01,27.94 IC18.14 | 165.1,64.77 163.83,63.5 IC29.14 | 175.26,64.77 165.1,64.77 | 175.26,64.77 176.53,63.5 IC36.14 | 175.26,64.77 190.5,64.77 191.77,63.5 IC35.14 | 165.1,64.77 146.69,64.77 145.41,63.5 SV1.1 | IC37.1 IC37.20 IC27.1 IC27.20 77.47,66.04 78.74,67.31 88.9,67.31 90.17,66.04 IC5.20 IC32.1 IC32.20 107.95,66.04 109.22,67.31 119.38,67.31 | 119.38,67.31 120.65,66.04 IC46.20 | 130.81,67.31 119.38,67.31 | 130.81,67.31 134.62,67.31 135.89,66.04 IC6.20 | 130.81,67.31 135.89,62.23 138.43,62.23 139.7,60.96 SV1.3 | v194.31,68.58 201.93,68.58 207.01,63.5 IC20.14
WAIT\  (1 unrouted)
WASMEM  (via drill 0.61)
  Top 0.254: v208.91,68.58 205.1,72.39 205.1,147.32 177.16,147.32 177.16,144.15 IC22.2
  Bottom 0.254: v208.91,68.58 210.19,68.58 210.19,55.24 209.55,54.61 203.2,54.61 201.93,53.34 IC20.5
WE\  (via drill 0.61)
  Top 0.254: v194.94,46.99 194.94,67.94 195.58,68.58 195.58,111.76 IC38.27
  Bottom 0.254: v194.94,46.99 180.34,46.99 179.07,48.26 IC36.8 | IC39.27 180.34,114.3 181.61,115.57 195.58,115.57 196.85,114.3 IC38.27
XTA  (via drill 0.61)
  Top 0.254: IC26.9 177.16,15.88 177.16,17.14 IC26.10 179.71,19.68 179.71,51.44 180.34,52.07 180.34,67.94 v180.97,68.58 | v148.59,67.94 148.59,55.24 147.32,53.98 SV1.10
  Bottom 0.254: IC26.10 IC15.5 | CPU.9 24.13,71.12 24.77,70.48 36.2,70.48 36.83,69.85 50.8,69.85 52.7,67.94 v148.59,67.94 149.22,68.58 154.94,68.58 155.57,67.94 166.37,67.94 167,68.58 v180.97,68.58
XTA\
  Top 0.254: IC26.8 175.26,15.24 175.26,58.42 IC36.13 | IC35.5 183.51,55.24 183.51,59.05 IC35.2
  Bottom 0.254: IC35.5 IC35.10 | IC36.13 IC35.2
XTB  (via drill 0.61)
  Top 0.254: v31.11,69.22 32.38,70.48 32.38,118.11 | 32.38,118.11 32.38,119.38 33.66,120.65 33.66,140.34 36.83,143.51 40.64,143.51 48.26,151.13 76.2,151.13 76.2,147.32 74.3,145.41 74.3,141.6 74.93,140.97 78.11,140.97 78.11,139.06 IC11.11 | IC26.12 177.16,23.5 177.16,24.77 IC26.13 | v150.5,26.67 149.22,27.94 149.22,48.26 147.32,50.16 SV1.12 | v134.62,61.59 134.62,77.47 135.89,78.74 135.89,87.63 135.25,88.27 135.25,89.53 135.89,90.17 139.7,90.17 139.7,95.25 142.24,97.79 142.24,111.12 v141.6,111.76 | v167,122.56 167,126.36 IC41.9 | v144.78,121.92 v144.78,116.2 IC9.1 | v203.84,26.67 204.47,27.3 204.47,62.87 203.2,64.14 v203.2,123.19 | v31.75,118.11 32.38,118.11
  Bottom 0.254: v31.11,69.22 29.84,69.22 24.13,63.5 CPU.12 | v150.5,26.67 175.26,26.67 176.53,25.4 IC26.13 179.07,25.4 180.34,26.67 v203.84,26.67 | v134.62,61.59 133.99,61.59 IC6.1 | IC9.1 v141.6,111.76 | v144.78,121.92 166.37,121.92 v167,122.56 168.28,123.83 180.34,123.83 180.97,123.19 v203.2,123.19 | v31.75,118.11 87.63,118.11 88.27,118.75 91.44,118.75 92.08,118.11 107.31,118.11 108.58,116.84 144.15,116.84 v144.78,116.2
XTB\  (via drill 0.61)
  Top 0.254: 175.9,44.45 175.9,51.44 IC36.10 | 175.9,44.45 175.9,22.23 IC26.11 | v120.02,146.69 120.02,144.15 IC16.13 | v209.55,135.89 209.55,104.78 212.09,102.23 v212.09,46.99 | v178.44,44.45 175.9,44.45
  Bottom 0.254: v120.02,146.69 120.65,146.05 123.19,146.05 123.83,145.41 127.64,145.41 128.27,146.05 164.47,146.05 165.1,145.41 165.74,145.41 167,146.69 198.75,146.69 v209.55,135.89 | v212.09,46.99 209.55,44.45 v178.44,44.45
XTC  (via drill 0.61)
  Top 0.254: v10.79,15.88 v10.79,59.69 | v55.88,16.51 56.52,15.88 56.52,7.62 58.42,5.71 65.41,5.71 66.67,6.99 74.3,6.99 v74.3,4.45 | v158.12,3.81 167,12.7 v167,48.26
  Bottom 0.254: v10.79,59.69 20.32,59.69 21.59,60.96 CPU.13 | v10.79,15.88 11.43,16.51 v55.88,16.51 | v74.3,4.45 74.93,5.08 130.81,5.08 132.08,3.81 v158.12,3.81 | v167,48.26 165.74,46.99 158.75,46.99 156.21,49.53 150.5,49.53 149.22,48.26 SV1.14
ZF  (1 unrouted)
